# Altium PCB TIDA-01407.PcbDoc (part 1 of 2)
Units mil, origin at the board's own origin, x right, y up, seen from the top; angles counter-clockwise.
Board outline 6000 x 3000 mil, 4 copper layers (Top Layer, Signal Layer 1, Signal Layer 2, Bottom Layer), stack 79.834 mil thick; 145 components, 63 nets, 415 pads, 195 vias.
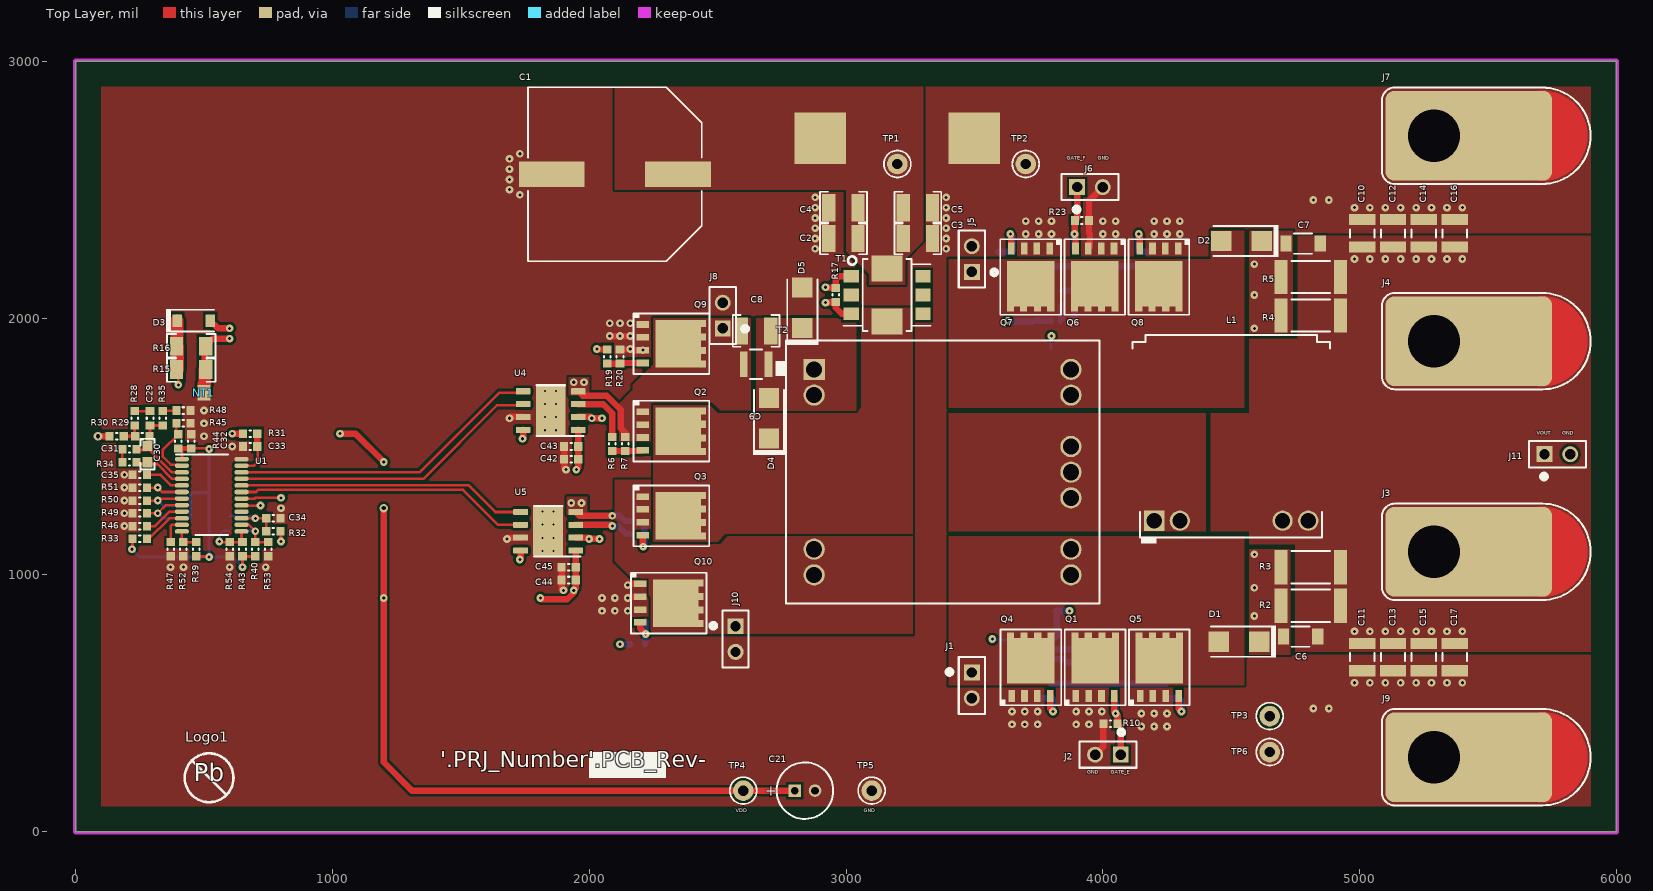
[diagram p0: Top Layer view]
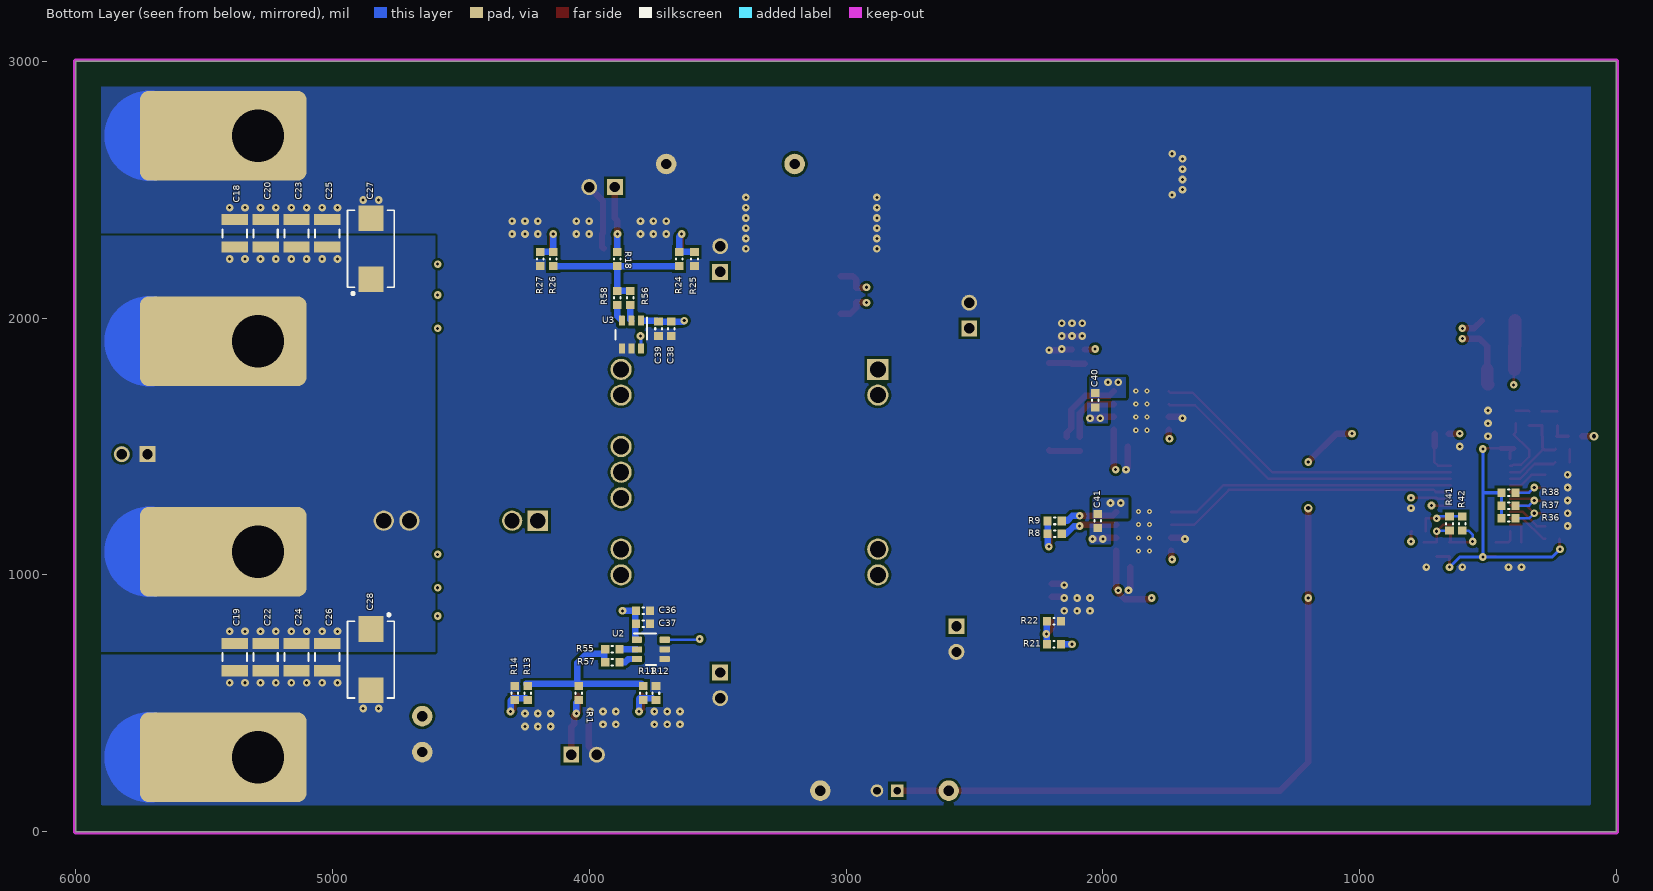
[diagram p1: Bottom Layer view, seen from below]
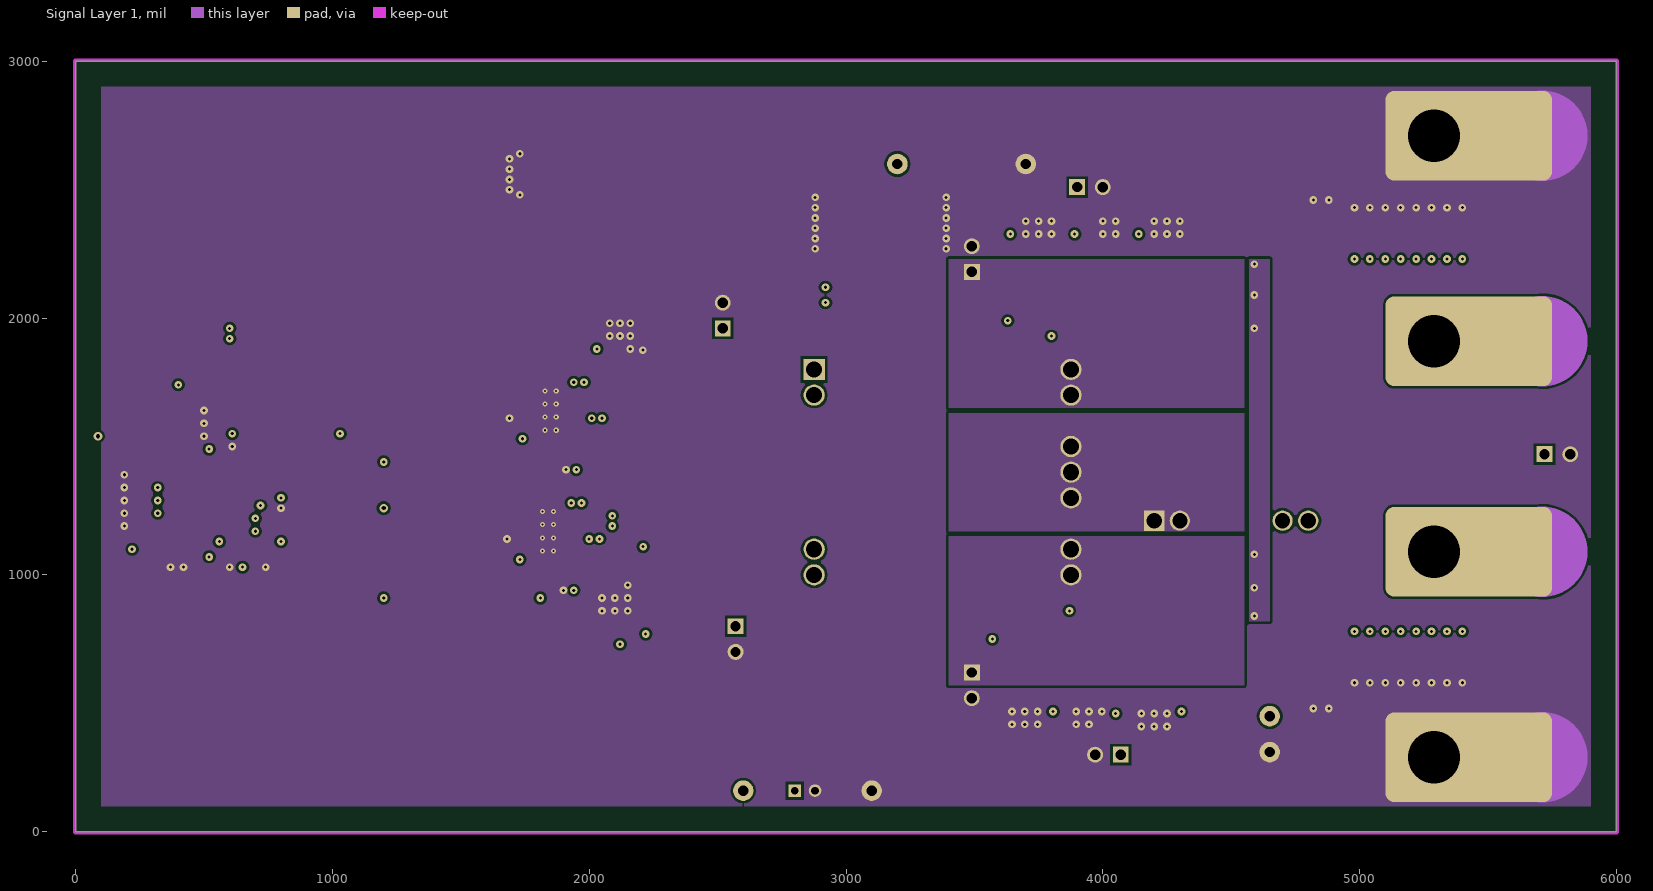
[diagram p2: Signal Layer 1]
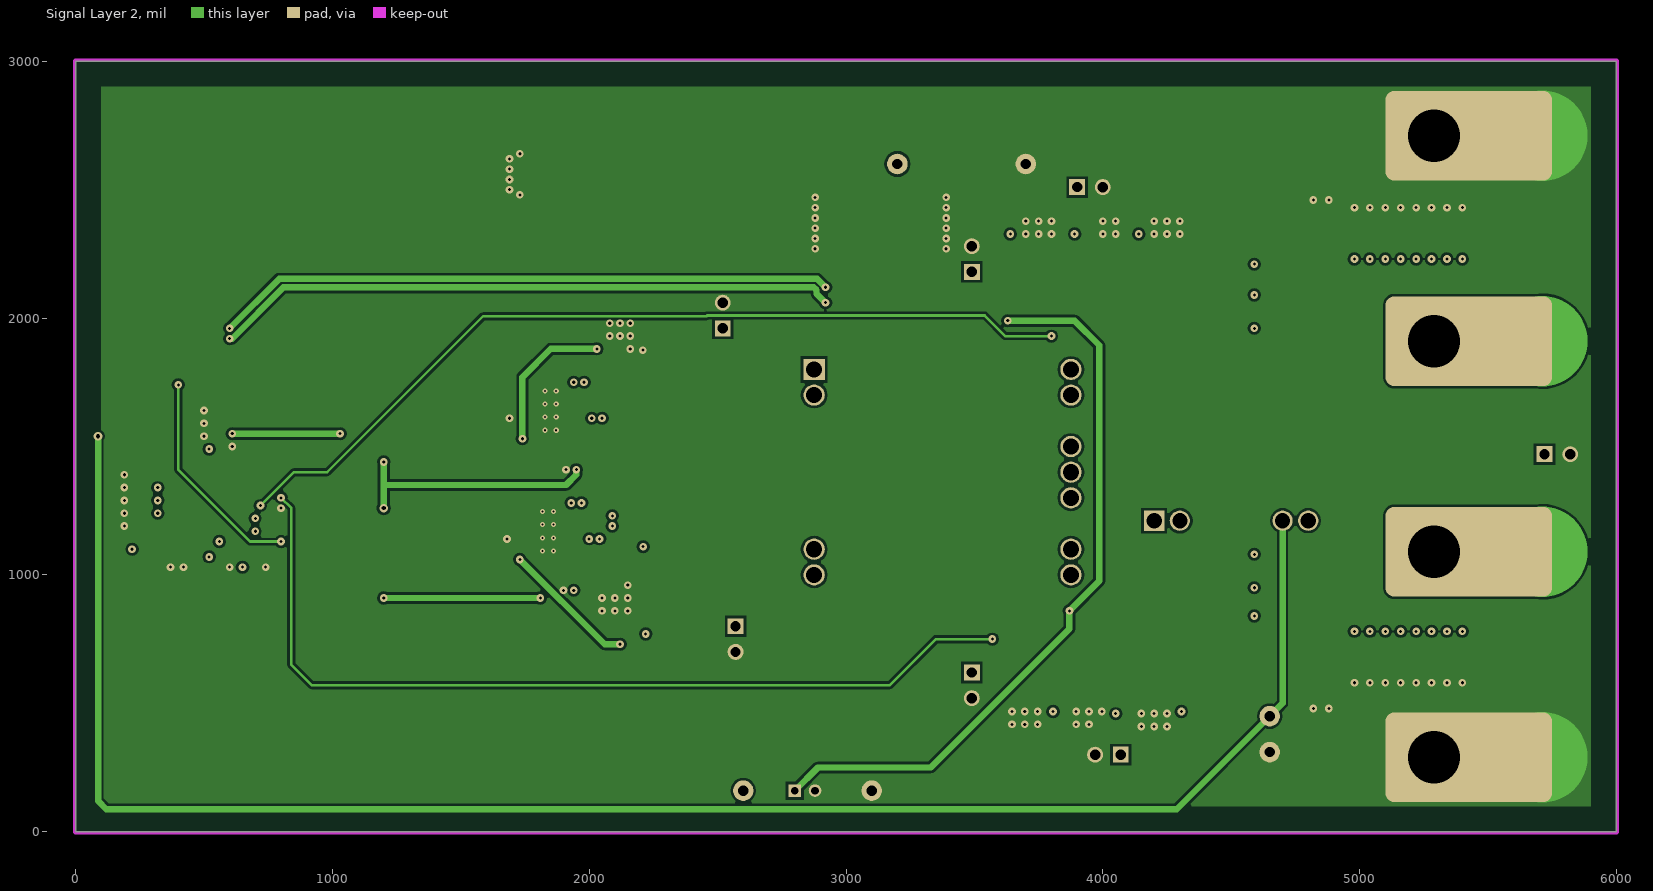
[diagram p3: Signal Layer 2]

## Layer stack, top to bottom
Top Solder: solder mask 0.4, Solder Resist, Dk 3.5
Top Layer: signal copper 1.4
Dielectric1: core 59.2, FR-4, Dk 4.8
Signal Layer 1: signal copper 1.417
Dielectric 3: prepreg 5, Dk 4.2
Signal Layer 2: signal copper 1.417
Dielectric 2: core 10, Dk 4.2
Bottom Layer: signal copper 1.4
Bottom Solder: solder mask 0.4, Solder Resist, Dk 3.5

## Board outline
0,0 6000,0 6000,3000 0,3000

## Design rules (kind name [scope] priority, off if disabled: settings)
AcuteAngle [All] p1: minimum=4.50000000000000E+0001 checktracksonly=FALSE
AssemblyTestPointUsage [All] p1: valid=2
Clearance Clearance_BoardEdge_MountingHoles [OnCopper and InComponentClass('Mounting Holes') vs IsKeepOut] p1: gap=40
Clearance Clearance_BoardEdge_Poly [OnCopper and InPoly vs IsKeepOut] p2: gap=25
Clearance Clearance_BoardEdge [OnCopper and Not InComponentClass('Logo') and not InComponentClass('FiducialMark') and not InRegion(1000,500,4000,800) and Not IsKeepout vs IsKeepOut] p3: gap=70
Clearance Clearance_Poly [InPolygon] p4: gap=10
Clearance [All] p5: gap=7.5
ComponentClearance ComponentClearance_ScrewToNut [(HasFootprint('NY PMS 440 0025 PH')) vs (HasFootprint('Keystone_1902C'))] p1: gap=5 collisioncheckmode=3 verticalgap=10 showdistances=FALSE
ComponentClearance ComponentClearance_MountingHoles [InComponentClass('Mounting Holes')] p2: gap=20 collisioncheckmode=3 verticalgap=100000 showdistances=FALSE
ComponentClearance ComponentClearance_SmallPassives [HasFootprint('0201*') or HasFootprint('0402*') or HasFootprint('0508') or HasFootprint('0603*') or HasFootprint('0612') or HasFootprint('0805*') or HasFootprint('0815*') or HasFootprint('0830*') or HasFootprint('1206*') or HasFootprint('1210*') or HasFootprint('1808*') or HasFootprint('1812*') or HasFootprint('1825*') or HasFootprint('2010*') or HasFootprint('2220*') or HasFootprint('2225*') or HasFootprint('2512*') or HasFootprint('2728*') or HasFootprint('3518*') vs HasFootprint('0201*') or HasFootprint('0402*') or HasFootprint('0508') or HasFootprint('0603*') or HasFootprint('0612') or HasFootprint('0805*') or HasFootprint('0815*') or HasFootprint('0830*') or HasFootprint('1206*') or HasFootprint('1210*') or HasFootprint('1808*') or HasFootprint('1812*') or HasFootprint('1825*') or HasFootprint('2010*') or HasFootprint('2220*') or HasFootprint('2225*') or HasFootprint('2512*') or HasFootprint('2728*') or HasFootprint('3518*')] p3: gap=10 collisioncheckmode=3 verticalgap=10 showdistances=FALSE
ComponentClearance ComponentClearance_THtoSMT [IsThruComponent vs IsSMTComponent] p4: gap=1 collisioncheckmode=3 verticalgap=0 showdistances=FALSE
ComponentClearance ComponentClearance_THtoTH [IsThruComponent vs IsThruComponent] p5: gap=20 collisioncheckmode=3 verticalgap=100000 showdistances=FALSE
ComponentClearance [All] p6: gap=20 collisioncheckmode=3 verticalgap=0 showdistances=FALSE
DiffPairsRouting [All] p1: maxlimit=100 minlimit=10 mostfreqgap=10 toplayer_minwidth=15 toplayer_maxwidth=15 toplayer_prefwidth=15 midlayer1_minwidth=15 midlayer1_maxwidth=15 midlayer1_prefwidth=15 midlayer2_minwidth=15 midlayer2_maxwidth=15 midlayer2_prefwidth=15 bottomlayer_minwidth=15 bottomlayer_maxwidth=15 bottomlayer_prefwidth=15 maxuncoupledlength=1000
FabricationTestPointUsage TestPointUsage [All] p1: valid=2 allowmultiple=FALSE
FabricationTestpoint Testpoint [All] p1: side=3 testpointundercomponent=TRUE minsize=40 maxsize=100 preferedsize=60 minholesize=0 maxholesize=40 preferedholesize=32 testpointgrid=1 allowsidetop=TRUE allowsidebottom=TRUE usegrid=TRUE gridtolerance=0.01
FanoutControl Fanout_LCC [IsLCC] p1: bgadir=Out bgaviamode=Centered fanoutstyle=Auto fanoutdirection=Alternating viagrid=1 // Fanout_LCC (Default Rule)
FanoutControl Fanout_BGA [IsBGA] p2: bgadir=Out bgaviamode=Centered fanoutstyle=Auto fanoutdirection=Alternating viagrid=1 // Fanout_BGA (Default Rule)
FanoutControl Fanout_Default [All] p4: bgadir=Out bgaviamode=Centered fanoutstyle=Auto fanoutdirection=Alternating viagrid=1 // Fanout_Default (Default Rule)
FanoutControl Fanout_Small [(CompPinCount < 5)] p5: bgadir=Out bgaviamode=Centered fanoutstyle=Auto fanoutdirection=OutThenIn viagrid=1 // Fanout_Small (Default Rule)
HoleSize [All] p1: absolutevalues=TRUE maxlimit=251 minlimit=7 maxpercent=80.000 minpercent=20.000
MinimumAnnularRing [All] p1: minimumring=5
MinimumSolderMaskSliver MinimumSolderMaskSliver_Logo [InComponentClass('Logo') vs InComponentClass('Logo')] p1: minsoldermaskwidth=0
MinimumSolderMaskSliver SilkscreenOverComponentPads [All] p2: minsoldermaskwidth=0
MinimumSolderMaskSliver [All] p3: minsoldermaskwidth=0
PlaneConnect [All] p1: planeconnectstyle=Direct reliefexpansion=10 reliefentries=4 reliefconductorwidth=10 reliefairgap=10
PolygonConnect [All] p1: connectstyle=Direct reliefconductorwidth=10 reliefentries=4 polygonreliefangle="90 Angle" airgapwidth=10
RoutingVias [All] p1: holewidth=16 width=34 viastyle="Through Hole" minholewidth=7 minwidth=19 maxholewidth=40 maxwidth=65
SMDToCorner [All] p1: distance=0
SilkToBoardRegionClearance [Not ((IsComment or IsDesignator) And (Hide <> 'False')) and not InRegion(1000,500,4000,800)] p1:
SilkToSilkClearance [All] p1: silktosilkclearance=0
SilkToSolderMaskClearance [IsPad] p1: minsilkscreentomaskgap=0 clearancetoexposedcopper=TRUE
SolderMaskExpansion [All] p1: expansion=3
Width [All] p1: maxlimit=100 minlimit=6 preferedwidth=10 checkconnectedcopper=TRUE
15 further rules are at their usual default settings.

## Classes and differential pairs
component class "Gate Drivers High Side and Low Side": C36 C37 C38 C39 C40 C41 C42 C43 C44 C45 C47 C48 C51 C52 C55 D8 D10 D11 D12 D13 D14 D15 D17 D18 D19 D20 D21 D22 D24 D25 Logo1 Q12 Q15 Q16 R55 R56 R57 R58 R62 R64 T5 U2 U3 U4 U5
component class "400W Phase Shifted Full Bridge": C1 C2 C3 C4 C5 C6 C7 C8 C9 C10 C11 C12 C13 C14 C15 C16 C17 C18 C19 C20 C21 C22 C23 C24 C25 C26 C27 C28 C29 C30 C31 C32 C33 C34 C35 D1 D2 D3 D4 D5 J1 J2 J3 J4 J5 J6 J7 J8 J9 J10 J11 L1 NT1 Q1 Q2 Q3 Q4 Q5 Q6 Q7 Q8 Q9 Q10 R1 R2 R3 R4 R5 R6 R7 R8 R9 R10 R11 R12 R13 R14 R15 R16 R17 R18 R19 R20 R21 R22 R23 R24 R25 R26 R27 R28 R29 R30 R31 R32 R33 R34 R35 R36 R37 R38 R39 R40 R41 R42 R43 R44 R45 R46 R47 R48 R49 R50 R51 R52 R53 R54 T1 T2 TP1 TP2 TP3 TP4 TP5 TP6 U1

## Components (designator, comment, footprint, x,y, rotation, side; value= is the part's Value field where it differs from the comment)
C1 "EEV-FK2A151M" SM_RADIAL_J16 2100,2560 r180 top
C2 "GRM32ER72A225KA35L" 1210_270 2990,2310 r180 top
C3 "GRM32ER72A225KA35L" 1210_270 3280,2310 r0 top
C4 "GRM32ER72A225KA35L" 1210_270 2990,2430 r180 top
C5 "GRM32ER72A225KA35L" 1210_270 3280,2430 r0 top
C6 "GRM31CR72E104KW03L" 1206_180 4770,760 r0 top
C7 "GRM31CR72E104KW03L" 1206_180 4780,2290 r0 top
C8 "GRM32ER72A225KA35L" 1210_270 2650,1950 r0 top
C9 "170nH Custom Shim" DFE322512C 2650,1820 r180 top
C10 "GRM32ER71E226KE15L" 1210_270L 5010,2330 r90 top
C11 "GRM32ER71E226KE15L" 1210_270L 5010,680 r270 top
C12 "GRM32ER71E226KE15L" 1210_270L 5130,2330 r90 top
C13 "GRM32ER71E226KE15L" 1210_270L 5130,680 r270 top
C14 "GRM32ER71E226KE15L" 1210_270L 5250,2330 r90 top
C15 "GRM32ER71E226KE15L" 1210_270L 5250,680 r270 top
C16 "GRM32ER71E226KE15L" 1210_270L 5370,2330 r90 top
C17 "GRM32ER71E226KE15L" 1210_270L 5370,680 r270 top
C18 "GRM32ER71E226KE15L" 1210_270L 5380,2330 r90 bottom
C19 "GRM32ER71E226KE15L" 1210_270L 5380,680 r270 bottom
C20 "GRM32ER71E226KE15L" 1210_270L 5260,2330 r90 bottom
C21 "EKZE350ELL330ME11D" Chemi-Con_500x1100 2840,160 r0 top
C22 "GRM32ER71E226KE15L" 1210_270L 5260,680 r270 bottom
C23 "GRM32ER71E226KE15L" 1210_270L 5140,2330 r90 bottom
C24 "GRM32ER71E226KE15L" 1210_270L 5140,680 r270 bottom
C25 "GRM32ER71E226KE15L" 1210_270L 5020,2330 r90 bottom
C26 "GRM32ER71E226KE15L" 1210_270L 5020,680 r270 bottom
C27 "16TQC150MYF" 7343-31 4850,2270 r90 bottom
C28 "16TQC150MYF" 7343-31 4850,670 r270 bottom
C29 "GRM1885C1H470JA01D" 0603L 290,1610 r90 top
C30 "GRM1885C1H331JA01D" 0603 280,1470 r90 top
C31 "GRM188R71H103KA01D" 0603L 210,1489.33 r0 top
C32 "GRM188R71E105KA12D" 0603L 450,1520 r90 top
C33 "GRM188R71E105KA12D" 0603L 680,1500 r180 top
C34 "GRM1885C1H821JA01D" 0603L 770,1220 r0 top
C35 "GRM188R71H473KA61D" 0603L 250,1390 r180 top
C36 "GRM188R71E105KA12D" 0603L 3790,860 r180 bottom
C37 "GRM188R71H104KA93D" 0603L 3790,810 r180 bottom
C38 "GRM188R71E105KA12D" 0603L 3680,1958.5 r270 bottom
C39 "GRM188R71H104KA93D" 0603L 3730,1958.5 r270 bottom
C40 "GRM188R71H104KA93D" 0603L 2030,1680 r90 bottom
C41 "GRM188R71H104KA93D" 0603L 2020,1210 r90 bottom
C42 "GRM188R71E105KA12D" 0603L 1930,1450 r180 top
C43 "GRM188R71H104KA93D" 0603L 1930,1500 r180 top
C44 "GRM188R71E105KA12D" 0603L 1920,980 r180 top
C45 "GRM188R71H104KA93D" 0603L 1920,1030 r180 top
D1 "ES1D" SMA 4530,740 r180 top
D2 "ES1D" SMA 4540,2300 r180 top
D3 "1N4148W-7-F" SOD-123 460,1990 r0 top
D4 "ES1D" SMA 2700,1610 r90 top
D5 "ES1D" SMA 2830,2040 r90 top
J1 "PPTC021LFBN-RC" CONN_PPTC021LFBN-RC 3490,570 r90 top
J2 "PPTC021LFBN-RC" CONN_PPTC021LFBN-RC 4020,300 r0 top
J3 "L35" TB_L35 5290,1090 r0 top
J4 "L35" TB_L35 5290,1910 r0 top
J5 "PPTC021LFBN-RC" CONN_PPTC021LFBN-RC 3490,2230 r270 top
J6 "PPTC021LFBN-RC" CONN_PPTC021LFBN-RC 3950,2510 r180 top
J7 "L35" TB_L35 5290,2710 r0 top
J8 "PPTC021LFBN-RC" CONN_PPTC021LFBN-RC 2520,2010 r270 top
J9 "L35" TB_L35 5290,290 r0 top
J10 "PPTC021LFBN-RC" CONN_PPTC021LFBN-RC 2570,750 r90 top
J11 "PPTC021LFBN-RC" CONN_PPTC021LFBN-RC 5770,1470 r180 top
L1 "59024" 59024 4500,1540 r90 top
Logo1 "Pb-Free Symbol" Pb-Free_Overlay_Medium 520,210 r0 top
NT1 "Net-Tie" Net-Tie_50milWide_30milLong 500,1710 r90 top net-tie
Q1 "BSC057N08NS3 G" PG-TDSON-8 3970,640 r90 top
Q2 "BSC072N08NS5" PG-TDSON-8 2320,1560 r0 top
Q3 "BSC072N08NS5" PG-TDSON-8 2320,1230 r0 top
Q4 "BSC057N08NS3 G" PG-TDSON-8 3720,640 r90 top
Q5 "BSC057N08NS3 G" PG-TDSON-8 4220,640 r90 top
Q6 "BSC057N08NS3 G" PG-TDSON-8 3968.54,2160 r270 top
Q7 "BSC057N08NS3 G" PG-TDSON-8 3718.54,2160 r270 top
Q8 "BSC057N08NS3 G" PG-TDSON-8 4218.54,2160 r270 top
Q9 "BSC072N08NS5" PG-TDSON-8 2320,1900 r0 top
Q10 "BSC072N08NS5" PG-TDSON-8 2310,890 r0 top
R1 "CRCW06032R20JNEA" 0603L 4040,540 r90 bottom
R2 "CRCW25125K10JNEH" 2512 4810,880 r180 top
R3 "CRCW25125K10JNEH" 2512 4810,1030 r180 top
R4 "CRCW25125K10JNEH" 2512 4810,2010 r180 top
R5 "CRCW25125K10JNEH" 2512 4810,2160 r180 top
R6 "CRCW06030000Z0EA" 0603L 2090,1510 r270 top
R7 "CRCW060310K0FKEA" 0603L 2140,1510 r270 top
R8 "CRCW06030000Z0EA" 0603L 2187.56,1160 r0 bottom
R9 "CRCW060310K0FKEA" 0603L 2187.56,1210 r0 bottom
R10 "CRCW060310K0FKEA" 0603L 4030,420 r0 top
R11 "CRCW06032R20JNEA" 0603L 3790,540 r270 bottom
R12 "CRCW060310K0FKEA" 0603L 3740,540 r270 bottom
R13 "CRCW06032R20JNEA" 0603L 4240,540 r270 bottom
R14 "CRCW060310K0FKEA" 0603L 4290,540 r270 bottom
R15 "CRCW120610R0FKEA" 1206 450,1800 r180 top
R16 "CRCW120649R9FKEA" 1206 450,1890 r180 top
R17 "CRCW060310K0FKEA" 0603L 2960,2090 r90 top
R18 "CRCW06032R20JNEA" 0603L 3890,2230 r270 bottom
R19 "CRCW06030000Z0EA" 0603L 2070,1850 r270 top
R20 "CRCW060310K0FKEA" 0603L 2120,1850 r270 top
R21 "CRCW06030000Z0EA" 0603L 2190,730 r0 bottom
R22 "CRCW060310K0FKEA" 0603L 2190,820 r0 bottom
R23 "CRCW060310K0FKEA" 0603L 3918.54,2380 r180 top
R24 "CRCW06032R20JNEA" 0603L 3650,2230 r90 bottom
R25 "CRCW060310K0FKEA" 0603L 3590,2230 r90 bottom
R26 "CRCW06032R20JNEA" 0603L 4140,2230 r90 bottom
R27 "CRCW060310K0FKEA" 0603L 4190,2230 r90 bottom
R28 "CRCW06030000Z0EA" 0603L 230,1610 r90 top
R29 "CRCW060313K3FKEA" 0603L 260,1540 r180 top
R30 "CRCW060349R9FKEA" 0603L 160,1540 r180 top
R31 "CRCW060310R0JNEA" 0603L 680,1550 r180 top
R32 "CRCW0603100RFKEA" 0603L 770,1170 r0 top
R33 "CRCW060318K2FKEA" 0603L 250,1140 r180 top
R34 "CRCW060310K0FKEA" 0603L 210,1439.33 r0 top
R35 "CRCW06031K96FKEA" 0603L 340,1610 r270 top
R36 "CRCW060310K0FKEA" 0603L 420,1220 r0 bottom
R37 "CRCW060310K0FKEA" 0603L 420,1270 r0 bottom
R38 "CRCW060310K0FKEA" 0603L 420,1320 r0 bottom
R39 "CRCW060319K1FKEA" 0603L 470,1100 r270 top
R40 "CRCW060310K0FKEA" 0603L 700,1100 r270 top
R41 "CRCW06030000Z0EA" 0603L 650,1200 r90 bottom
R42 "CRCW06030000Z0EA" 0603L 600,1200 r90 bottom
R43 "CRCW060310K0FKEA" 0603L 650,1100 r270 top
R44 "CRCW060310K0FKEA" 0603L 400,1520 r270 top
R45 "CRCW060310K0FKEA" 0603L 420,1590 r180 top
R46 "CRCW060360K4FKEA" 0603L 250,1190 r0 top
R47 "CRCW060320K0FKEA" 0603L 370,1100 r90 top
R48 "CRCW06031K54FKEA" 0603L 420,1640 r180 top
R49 "RC0603FR-0713KL" 0603L 250,1239.33 r0 top
R50 "RC0603FR-0713KL" 0603L 250,1289.33 r0 top
R51 "RC0603FR-0713KL" 0603L 250,1339.33 r0 top
R52 "CRCW06031K00FKEA" 0603L 420,1100 r90 top
R53 "CRCW060310K0FKEA" 0603L 750,1100 r90 top
R54 "CRCW060310K0FKEA" 0603L 600,1100 r90 top
R55 "CRCW06030000Z0EA" 0603L 3910,710 r180 bottom
R56 "CRCW06030000Z0EA" 0603L 3840,2078.5 r270 bottom
R57 "CRCW06030000Z0EA" 0603L 3910,660 r180 bottom
R58 "CRCW06030000Z0EA" 0603L 3890,2078.5 r270 bottom
T1 "PA1005.100NL" P82xx 3160,2090 r0 top
T2 "59023" Payton_59023 3375.98,1400 r0 top
TP1 "5000" Keystone5000 3200,2600 r0 top
TP2 "5001" Keystone5001 3700,2600 r0 top
TP3 "5000" Keystone5000 4650,450 r0 top
TP4 "5000" Keystone5000 2600,160 r0 top
TP5 "5001" Keystone5001 3100,160 r0 top
TP6 "5001" Keystone5001 4650,310 r0 top
U1 "UCC28951-Q1" PW0024A_N 530,1310 r0 top
U2 "UCC27511A-Q1" DBV0006A_N 3760,710 r180 bottom
U3 "UCC27511A-Q1" DBV0006A_N 3835.67,1935.81 r270 bottom
U4 "UCC27212A-Q1" DDA0008E_N 1850,1640 r180 top
U5 "UCC27212A-Q1" DDA0008E_N 1840,1170 r180 top

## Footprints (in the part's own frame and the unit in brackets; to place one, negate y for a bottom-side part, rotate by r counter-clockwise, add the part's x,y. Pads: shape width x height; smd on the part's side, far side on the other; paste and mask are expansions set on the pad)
0603 [mm] "0603 from SM-752 data"
  rect 1x0.95 smd: 1(-0.8,0) 2(0.8,0)
  silkscreen extent -1.52,-0.69 1.52,0.69, body extent -0.87,-0.47 0.87,0.47, height 1
0603L [mm] "0603 from SM-752 data"
  rect 0.8x0.85 smd: 1(-0.7,0) 2(0.7,0)
  silkscreen extent -0.07,-0.33 0.07,0.33, body extent -0.87,-0.47 0.87,0.47, height 1
1206 [mm] "1206 from SM-752 data"
  rect 1.3x1.85 smd: 1(-1.45,0) 2(1.45,0)
  silkscreen extent -2.4,-1.21 2.4,1.21, body extent -1.7,-0.9 1.7,0.9, height 1.35
1206_180 [mm] "1206_180"
  rect 1.1x1.6 smd: 1(-1.7,0) 2(1.7,0)
  silkscreen extent -0.9,-1 0.9,1, body extent -1.75,-0.95 1.75,0.95, height 1.8
1210_270 [mm] "1210"
  rect 1.3x2.7 smd: 1(-1.45,0) 2(1.45,0)
  silkscreen extent -2.32,-1.57 2.32,1.57, body extent -1.7,-1.35 1.7,1.35, height 2.7
1210_270L [mm] "1210"
  rect 1.1x2.6 smd: 1(-1.35,0) 2(1.35,0)
  silkscreen extent -0.4,-1.2 0.4,1.2, body extent -1.7,-1.35 1.7,1.35, height 2.7
2512 [mm] "Chip Resistor, Body 6.3x3.2mm, IPC Medium Density"
  rect 1.3x3.4 smd: 1(-2.95,0) 2(2.95,0)
  silkscreen extent -1.9,-1.6 1.9,1.6, body extent -3.22,-1.67 3.22,1.67, height 0.71
7343-31 [mm] "Medium Density based on Kemet T495 dimensions"
  rect 2.55x2.45 smd: 1(-3.025,0) 2(3.025,0)
  silkscreen extent -4.56,-2.3 3.8,2.3, body extent -3.8,-2.3 3.8,2.3, height 3.1
59024 [mm] "TH, 4-Leads, Body 20x19.5mm"
  rect 2x2 hole 1.5: 1(-8.355,7.62)
  round 2 hole 1.5: 2(-8.355,5.08) 6(-8.355,-5.08) 7(-8.355,-7.62)
  silkscreen extent -10.6,-9.75 10,9.75, body extent -10,-9.75 10,9.75, height 12
Chemi-Con_500x1100 [mm] "TH, 2-Leads, Dia 5mm, Lead Sapcing 2mm"
  rect 1.25x1.25 hole 0.75: 1(-1,0)
  round 1.25 hole 0.75: 2(1,0)
  silkscreen extent -2.8,-2.8 2.8,2.8, body extent -2.75,-2.75 2.75,2.75, height 12.5
CONN_PPTC021LFBN-RC [mil] "SULLINS"
  rect 62x62 hole 40: 1(50,0)
  round 62 hole 40.16: 2(-50,0)
  silkscreen extent -111,-51 111,97, body extent -110,-50 110,50, height 336
DBV0006A_N [mm] "SOT23, 6-Leads, Body 2.9x1.6mm, Pitch 0.95mm, Lead Span 2.8mm, IPC Medium Density"
  rrect17% 1x0.6 smd: 1(-1.375,0.95) 2(-1.375,0) 3(-1.375,-0.95) 4(1.375,-0.95) 5(1.375,0) 6(1.375,0.95)
  silkscreen extent -1.68,-1.55 0.5,1.55, body extent -1.42,-1.46 1.42,1.46, height 1.12
DDA0008E_N [mm]
  rrect17% 1.45x0.6 smd: 1(-2.725,1.905) 2(-2.725,0.635) 3(-2.725,-0.635) 4(-2.725,-1.905) 5(2.725,-1.905) 6(2.725,-0.635) 7(2.725,0.635) 8(2.725,1.905)
  rrect7% 2.95x4.9 smd paste-1.5 mask-1.5: 9(0,0)
  rrect4% 2.4x3.1 on Top Paste: 9(0,0)
  rrect4% 2.4x3.1 on Top Solder: 9(0,0)
  silkscreen extent -3.22,-2.5 1.4,2.5, body extent -3,-2.45 3,2.45, height 1.57
DFE322512C [mm] "TOKO, Pad sizes increased as per request"
  rect 0.75x2.5 smd: 1(-1.225,0) 2(1.225,0)
  silkscreen extent -0.6,-1.45 0.6,1.45, body extent -1.7,-1.35 1.7,1.35, height 1.2
Keystone5000 [mil] "For Keystone 500x miniature loop terminals"
  round 80 hole 40: 1(0,0)
  silkscreen extent -52,-52 52,52, body extent -49,-49 49,49, height 182
Keystone5001 [mil] "For Keystone 500x miniature loop terminals"
  round 80 hole 40: 1(0,0)
  silkscreen extent -52,-52 52,52, body extent -49,-49 49,49, height 182
Net-Tie_50milWide_30milLong [mil] "50mil net tie, no solder mask opening, no solder paste"
  rect 30x50 smd paste-20 mask-20: 1(-15,0) 2(15,0)
P82xx [mil] "Pulse recommended land pattern"
  rect 60x50 smd: 1(-140,73) 2(-140,0) 3(-140,-73) 4(140,-73) 5(140,0) 6(140,73)
  rect 120x100 smd: 7(0,-103) 8(0,103)
  silkscreen extent -170,-140 170,150, body extent -95,-140 95,140, height 215
Payton_59023 [mm] "TH, 11-Leads, Body 31x26mm, Pitch 2.54mm"
  rect 2.1x2.1 hole 1.6: 1(-12.7,10.16)
  round 2.1 hole 1.6: 2(-12.7,7.62) 8(-12.7,-7.62) 9(-12.7,-10.16) 10(12.7,-10.16) 11(12.7,-7.62) 13(12.7,-2.54) 14(12.7,0) 15(12.7,2.54) 17(12.7,7.62) 18(12.7,10.16)
  silkscreen extent -16.5,-13 15.5,13, body extent -15.5,-13 15.5,13, height 18
Pb-Free_Overlay_Medium [mil]
  silkscreen extent -95,-95 95,95
PG-TDSON-8 [mm] "Infineon recommended land pattern"
  rect 1.2x0.65 smd: 1(-2.825,1.905) 2(-2.825,0.635) 3(-2.825,-0.635) 4(-2.825,-1.905)
  rect 0.5x0.7 smd: 5(3.175,-2) 6(3.175,-0.675) 7(3.175,0.675) 8(3.175,2)
  rect 4.5x4.7 smd paste-2.25: 9(0.675,0)
  silkscreen extent -3.74,-3 3.74,3, body extent -3.17,-2.89 3.17,2.9, height 1.1
PW0024A_N [mm] "TSOP, 24-Leads, Body 7.8x4.4mm, Pitch 0.65mm, IPC Medium Density"
  oval 1.4x0.45 smd: 1(-2.95,3.575) 2(-2.95,2.925) 3(-2.95,2.275) 4(-2.95,1.625) 5(-2.95,0.975) 6(-2.95,0.325) 7(-2.95,-0.325) 8(-2.95,-0.975) 9(-2.95,-1.625) 10(-2.95,-2.275) 11(-2.95,-2.925) 12(-2.95,-3.575) 13(2.95,-3.575) 14(2.95,-2.925) 15(2.95,-2.275) 16(2.95,-1.625) 17(2.95,-0.975) 18(2.95,-0.325) 19(2.95,0.325) 20(2.95,0.975) 21(2.95,1.625) 22(2.95,2.275) 23(2.95,2.925) 24(2.95,3.575)
  silkscreen extent -3.51,-3.95 1.6,4.04, body extent -3.21,-3.9 3.21,3.9, height 1
SM_RADIAL_J16 [mm] "16 x 16.5mm:  Panasonic J16"
  rect 6.5x2.5 smd: 1(-6.25,0) 2(6.25,0)
  silkscreen extent -8.6,-8.6 8.6,8.6, body extent -8.6,-8.6 8.6,8.6, height 17
SMA [mm] "Molded Diode, 2-Leads, Body 4.3x2.6mm, IPC Medium Density, based on OnSemi component dimensions and land pattern"
  rect 2x2 smd: 1(-2,0) 2(2,0)
  silkscreen extent -3.66,-1.57 2.79,1.57, body extent -2.6,-1.3 2.6,1.3, height 2.42
SOD-123 [mm] "On Semi recommended land pattern"
  rect 0.915x1.22 smd: 1(-1.637,0) 2(1.637,0)
  silkscreen extent -2.74,-1.17 2.03,1.17, body extent -1.93,-0.9 1.93,0.9, height 1.35
TB_L35 [mm] "Connector, L Type Copper Single Conductor, TH"
  rrect20% 16.51x8.89 hole 5.16 copper offset 3.429,0: 1(0,0)
  Multi-Layer circle w4.47: c10.7,0 r2.235
  silkscreen extent -5.16,-4.76 15.48,4.76, body extent -5.16,-4.76 15.48,4.76, height 9.53

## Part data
C1: "CAP, AL, 150 μF, 100 V, +/- 20%, 0.17 ohm, AEC-Q200 Grade 2, SMD"
C2 C3 C4 C5 C8: "CAP, CERM, 2.2 μF, 100 V, +/- 10%, X7R, 1210"
C6 C7: "CAP, CERM, 0.1 μF, 250 V, +/- 10%, X7R, 1206"
C9: library part 1277AS-H-R68M=P2, "Inductor, Flat Wire, 680 nH, 3.5 A, 0.035 ohm, SMD"
C10 C11 C12 C13 C14 C15 C16 C17 C18 C19 C20 C22 C23 C24 C25 C26: "CAP, CERM, 22 μF, 25 V, +/- 10%, X7R, 1210"
C21: "CAP, AL, 33 μF, 35 V, +/- 20%, TH"
C27 C28: "CAP, Tantalum Polymer, 150 μF, 16 V, +/- 20%, 0.05 ohm, 7343-31 SMD"
C29: "CAP, CERM, 47 pF, 50 V, +/- 5%, C0G/NP0, 0603"
C30: "CAP, CERM, 330 pF, 50 V, +/- 5%, C0G/NP0, 0603"
C31: "CAP, CERM, 0.01 μF, 50 V, +/- 10%, X7R, 0603"
C32 C33 C36 C38 C42 C44: "CAP, CERM, 1 μF, 25 V, +/- 10%, X7R, 0603"
C34: "CAP, CERM, 820 pF, 50 V, +/- 5%, C0G/NP0, 0603"
C35: "CAP, CERM, 0.047 μF, 50 V, +/- 10%, X7R, 0603"
C37 C39 C40 C41 C43 C45: "CAP, CERM, 0.1 μF, 50 V, +/- 10%, X7R, 0603"
D1 D2 D4 D5: library part ES1D-13-F, "Diode, Ultrafast, 200 V, 1 A, SMA"
D3: "Diode, Ultrafast, 100 V, 0.15 A, SOD-123"
J1 J2 J5 J6 J8 J10 J11: "Receptacle, 100mil, 2x1, Tin, TH"
J3 J4 J7 J9: "Connector, L Type Copper Single Conductor, TH"
L1: "Inductor, 1 μH, 47 A, TH"
Logo1: library part Pb-Free
NT1: "Single point connection between nets."
Q1 Q4 Q5 Q6 Q7 Q8: "MOSFET, N-CH, 80 V, 100 A, PG-TDSON-8"
Q2 Q3 Q9 Q10: library part BSC072N08NS5ATMA1, "MOSFET, N-CH, 80 V, 74 A, PG-TDSON-8"
R1 R11 R13 R18 R24 R26: "RES, 2.2, 5%, 0.1 W, 0603"
R2 R3 R4 R5: "RES, 5.1 k, 5%, 1 W, AEC-Q200 Grade 0, 2512"
R6 R8 R19 R21 R28 R41 R42 R55 R56 R57 R58: "RES, 0, 5%, 0.1 W, 0603"
R7 R9 R10 R12 R14 R17 R20 R22 R23 R25 R27 R34 R36 R37 R38 R40 R43 R44 R45 R53 R54: "RES, 10.0 k, 1%, 0.1 W, 0603"
R15: "RES, 10.0, 1%, 0.25 W, 1206"
R16: "RES, 49.9, 1%, 0.25 W, 1206"
R29: "RES, 13.3 k, 1%, 0.1 W, 0603"
R30: "RES, 49.9, 1%, 0.1 W, 0603"
R31: "RES, 10, 5%, 0.1 W, 0603"
R32: "RES, 100, 1%, 0.1 W, 0603"
R33: "RES, 18.2 k, 1%, 0.1 W, 0603"
R35: "RES, 1.96 k, 1%, 0.1 W, 0603"
R39: "RES, 19.1 k, 1%, 0.1 W, 0603"
R46: "RES, 60.4 k, 1%, 0.1 W, 0603"
R47: "RES, 20.0 k, 1%, 0.1 W, 0603"
R48: "RES, 1.54 k, 1%, 0.1 W, 0603"
R49 R50 R51: "RES, 13.0 k, 1%, 0.1 W, 0603"
R52: "RES, 1.00 k, 1%, 0.1 W, 0603"
T1: "SMT Current Sense Tranformer"
T2: "Transformer, TH"
TP1 TP3 TP4: "Test Point, Miniature, Red, TH"
TP2 TP5 TP6: "Test Point, Miniature, Black, TH"
U1: library part UCC28950PWR, "Green Phase-Shifted Full-Bridge Controller with Synchronous Rectification with Current Mode Control, 97 % Duty Cycle, -40 to +125 degC, 24-pin TSSOP (PW), Green (RoHS & no Sb/Br)"
U2 U3: library part UCC27511DBVR, "Single-Channel High-Speed Low-Side Gate Driver (with 4-A Peak Source and 8-A Peak Sink), DBV0006A (SOT-6)"
U4 U5: library part UCC27211AQDDARQ1, "120-V Boot, 4-A Peak, High Frequency High-Side and Low-Side Driver, DDA0008E (SOIC-8)"

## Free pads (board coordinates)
  rect 200x200 smd: 0(2900,2700) 0(3500,2700)

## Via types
v1: diameter 30, hole 12, Top Layer to Bottom Layer, 177 vias
v2: diameter 19.68, hole 7.87, Top Layer to Bottom Layer, tented both sides, 8 vias
v3: diameter 19.68, hole 7.87, Top Layer to Bottom Layer, 8 vias
v4: diameter 34, hole 16, Top Layer to Bottom Layer, 2 vias

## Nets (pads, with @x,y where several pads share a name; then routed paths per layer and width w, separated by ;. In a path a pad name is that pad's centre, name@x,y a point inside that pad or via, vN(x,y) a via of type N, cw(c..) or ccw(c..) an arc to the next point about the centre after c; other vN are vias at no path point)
10V_VDD: C21.1 C36.1 C37.1 C38.1 C39.1 C42.1 C43.1 C44.1 C45.1 R31.2 TP4.1 U2.1 U3.1 U4.1 U5.1 | length 8567.7
  Top Layer w25: v1(610,1550) R31.2@652.44,1550 ; v1(1030,1550) 1090,1550 v1(1200,1440) ; v4(1200,1260) v1(1200,910) 1200,270 1310,160 TP4.1@2600,160 C21.1@2800.63,160 ; v1(1810,910) 1815,905 1914.5,905 1940,930.5 v1(1940,940) 1947.56,947.56 C44.1@1947.56,980 C45.1@1947.56,1030 1947.56,1094.72 U5.1@1947.28,1095 ; v1(1950,1410) 1957.56,1417.56 C42.1@1957.56,1450 C43.1@1957.56,1500 1957.56,1564.72 U4.1@1957.28,1565
  Signal Layer 2 w25: v1(610,1550) v1(1030,1550) ; v1(1200,910) v1(1810,910) ; v4(1200,1260) 1200,1350 ; v1(1200,1440) 1200,1350 ; v1(1950,1410) 1950,1390 1910,1350 1200,1350 ; C21.1@2800.63,160 2890.63,250 3330,250 3870,790 v1(3870,860) 3986.22,976.22 3986.22,1893.78 3890,1990 v1(3630,1990)
  Bottom Layer w25: v1(3630,1990) 3633.94,1986.06 C38.1@3680,1986.06 C39.1@3730,1986.06 3733.88,1989.94 U3.1@3798.27,1989.94 ; U2.1@3817.29,755.35 3820.72,758.78 C36.1@3820.72,860 ; C36.1@3817.56,860 C36.1@3820.72,860 ; v1(3870,860) C36.1@3820.72,860
ADEL: R40.1 R41.1 R53.2 U1.14 | length 207.6
  Top Layer w10: U1.14@646.14,1194.84 675.16,1194.84 v1(700,1170) R40.1@700,1127.56 R53.2@750,1127.56
  Bottom Layer w10: R41.1@650,1172.44 697.56,1172.44 v1(700,1170)
ADELEF: R42.1 R43.1 R54.2 U1.13 | length 207.6
  Top Layer w10: v1(560,1130) 562.44,1127.56 R54.2@600,1127.56 R43.1@650,1127.56 646.14,1131.42 U1.13@646.14,1169.25
  Bottom Layer w10: v1(560,1130) 560,1156.89 575.55,1172.44 R42.1@600,1172.44
CS: D3.1 R15.2 R16.2 R32.2 | length 1139.2
  Top Layer w10: R15.2@396.85,1800 400,1796.85 v1(400,1740) ; R32.2@797.56,1170 800,1167.56 v1(800,1130)
  Top Layer w50: D3.1@395.53,1990 395.53,1891.32 396.85,1890 R15.2@396.85,1800
  Signal Layer 2 w10: v1(400,1740) 400,1409.33 679.33,1130 v1(800,1130)
CS_FLT: C34.1 R32.1 R41.2 R42.2 U1.15 | length 249.6
  Top Layer w10: U1.15@646.14,1220.43 646.57,1220 v1(700,1220) C34.1@742.44,1220 R32.1@742.44,1170
  Bottom Layer w10: R42.2@600,1227.56 R41.2@650,1227.56 692.44,1227.56 v1(700,1220)
DCM: R39.1 R52.2 U1.12 | length 94.2
  Top Layer w10: U1.12@413.86,1169.25 413.86,1133.7 R52.2@420,1127.56 R39.1@470,1127.56
DELAB: R38.1 R51.2 U1.6 | length 224.4
  Top Layer w10: R51.2@277.56,1339.33 278.23,1340 v1(320,1340) 337.2,1322.8 U1.6@413.86,1322.8
  Bottom Layer w10: v1(320,1340) 340,1320 R38.1@392.44,1320
DELCD: R37.1 R50.2 U1.7 | length 220.3
  Top Layer w10: R50.2@277.56,1289.33 319.33,1289.33 v1(320,1290) 327.2,1297.2 U1.7@413.86,1297.2
  Bottom Layer w10: v1(320,1290) 340,1270 R37.1@392.44,1270
DELEF: R36.1 R49.2 U1.8 | length 230.4
  Top Layer w10: R49.2@277.56,1239.33 319.33,1239.33 v1(320,1240) 351.61,1271.61 U1.8@413.86,1271.61
  Bottom Layer w10: v1(320,1240) 340,1220 R36.1@392.44,1220
DRV_A: R6.1 U4.3 | length 239.7
  Top Layer w25: U4.3@1957.28,1665 2055,1665 2090,1630 R6.1@2090,1537.56
DRV_B: R19.1 U4.8 | length 652.7
  Top Layer w25: v1(1740,1530) 1742.72,1532.72 U4.8@1742.72,1565 ; v1(2030,1880) 2032.44,1877.56 R19.1@2070,1877.56
  Signal Layer 2 w25: v1(1740,1530) 1740,1770 1850,1880 v1(2030,1880)
DRV_C: R8.1 U5.3 | length 227.2
  Top Layer w25: U5.3@1947.28,1195 2085,1195 v1(2090,1190)
  Bottom Layer w25: v1(2090,1190) 2113.27,1190 2143.27,1160 R8.1@2160,1160
DRV_D: R21.1 U5.8 | length 605.3
  Top Layer w25: v1(1730,1060) 1732.72,1062.72 U5.8@1732.72,1095
  Signal Layer 2 w25: v1(1730,1060) 2060,730 v1(2120,730)
  Bottom Layer w25: v1(2120,730) R21.1@2162.44,730
DRV_E: R1.2 R11.1 R13.1 R55.1 R57.1 | length 702.4
  Bottom Layer w25: R11.1@3796.19,575.51 R1.2@4046.19,575.51 ; 3940.72,692.95 3941.5,692.95 ; R57.1@3941.5,660 3941.5,692.95 ; R55.1@3941.5,710 3941.5,692.95 ; R13.1@4246.19,575.51 R1.2@4046.19,575.51 ; 3941.5,692.95 4011.19,692.95 4046.19,657.95 R1.2@4046.19,575.51
DRV_F: R18.2 R24.1 R26.1 R56.1 R58.1 | length 876.4
  Bottom Layer w25: R56.1@3840,2106.06 R58.1@3890,2106.06 R18.2@3890,2202.44 ; R26.1@4140,2202.44 R18.2@3890,2202.44 ; R18.2@3890,2202.44 R24.1@3650,2202.44 R18.2@3890,2202.44
EA+: R44.1 R45.2 U1.2 | length 246.3
  Top Layer w10: R45.2@392.44,1590 392.44,1555.12 R44.1@400,1547.56 340,1487.56 340,1460 370.61,1429.39 400.77,1429.39 405,1425.16 U1.2@413.86,1425.16
FB: C29.1 C30.2 C31.2 R29.1 R35.2 U1.3 | length 363.2
  Top Layer w10: C30.2@280,1486.89 287.86,1486.89 375.18,1399.57 U1.3@413.86,1399.57
  Top Layer w12: C31.2@237.56,1489.33 240,1486.89 280,1486.89 287.56,1494.45 R29.1@287.56,1540 290,1542.44 C29.1@290,1582.44 R35.2@340,1582.44
GND: C1.2 C2.2 C3.2 C4.2 C5.2 C10.2 C11.2 C12.2 C13.2 C14.2 C15.2 C16.2 C17.2 C18.2 C19.2 C20.2 C21.2 C22.2 C23.2 C24.2 C25.2 C26.2 C27.2 C28.2 C32.2 C33.2 C34.2 C35.2 C36.2 C37.2 C38.2 C39.2 C42.2 C43.2 C44.2 C45.2 D5.2 J1.2 J2.2 J5.2 J6.2 J7.1 J8.2 J9.1 J10.2 J11.2 NT1.1 pad.0@3500,2700 Q1.1 Q1.2 Q1.3 Q4.1 Q4.2 Q4.3 Q5.1 Q5.2 Q5.3 Q6.1 Q6.2 Q6.3 Q7.1 Q7.2 Q7.3 Q8.1 Q8.2 Q8.3 Q9.1 Q9.2 Q9.3 Q10.1 Q10.2 Q10.3 R10.1 R12.1 R14.1 R20.1 R22.1 R23.1 R25.1 R27.1 R45.1 R46.1 R47.1 R48.1 R49.1 R50.1 R51.1 R52.1 R53.1 R54.1 TP2.1 TP5.1 TP6.1 U1.24 U2.4 U2.5 U3.4 U3.5 U4.7 U4.9@1850,1640 U5.7 U5.9@1840,1170 | length 977
  Top Layer w25: v1(1680,1140) 1685,1145 U5.7@1732.72,1145 ; v1(1690,1610) 1695,1615 U4.7@1742.72,1615 ; C45.2@1892.44,1030 C44.2@1892.44,980 1892.44,947.56 v1(1900,940) ; C43.2@1902.44,1500 C42.2@1902.44,1450 1902.44,1417.56 v1(1910,1410) ; v1(2080,1930) v1(2160,1930) v1@2165,1925 ; R20.1@2120,1877.56 2157.56,1877.56 v1(2160,1880) 2165,1875 v1(2208.78,1875) ; v1@2148.32,960 v1(2150,960) 2155,965 Q10.1@2198.78,965 ; v1(2150,910) 2155,915 Q10.2@2198.78,915 ; Q6.3@3943.54,2271.22 3950,2277.68 3950,2327.33 3946.1,2331.23 R23.1@3946.1,2380 3946.1,2456.1 J6.2@4000,2510 ; J2.2@3970,300 4002.44,332.44 R10.1@4002.44,420
  other v1: 4150,410 4200,410 4250,410 3646.19,417.95 3696.19,417.95 3746.19,417.95 3896.19,417.95 3946.19,417.95 4150,460 4200,460 4250,460 3646.19,467.95 3696.19,467.95 3746.19,467.95 3896.19,467.95 3946.19,467.95 3996.19,467.95 4820,480 4880,480 4980,580 5040,580 5100,580 5160,580 5220,580 5280,580 5340,580 5400,580 2050,860 2100,860 2150,860 2050,910 2100,910 370,1030 420,1030 600,1030 740,1030 190,1190 190,1240 800,1260 190,1290 190,1340 190,1390 610,1500 500,1540 500,1590 500,1640 2120,1930 2080,1980 2120,1980 2160,1980 2880,2270 3390,2270 2880,2310 3390,2310 3700,2327.33 3750,2327.33 3800,2327.33 4000,2327.33 4050,2327.33 4200,2327.33 4250,2327.33 4300,2327.33 2880,2350 3390,2350 3700,2377.33 3750,2377.33 3800,2377.33 4000,2377.33 4050,2377.33 4200,2377.33 4250,2377.33 4300,2377.33 2880,2390 3390,2390 2880,2430 3390,2430 4980,2430 5040,2430 5100,2430 5160,2430 5220,2430 5280,2430 5340,2430 5400,2430 4820,2460 4880,2460 2880,2470 3390,2470 1730,2480 1690,2500 1690,2540 1690,2580 1690,2620 1730,2640
  other v2: 1818.35,1093.23 1861.65,1093.23 1818.35,1246.77 1861.65,1246.77 1828.35,1563.23 1871.65,1563.23 1828.35,1716.77 1871.65,1716.77
  other v3: 1818.35,1144.41 1861.65,1144.41 1818.35,1195.59 1861.65,1195.59 1828.35,1614.41 1871.65,1614.41 1828.35,1665.59 1871.65,1665.59
NetC1_1: C1.1 C2.1 C3.1 C4.1 C5.1 pad.0@2900,2700 T1.8 TP1.1
NetC6_1: C6.1 C7.1 D1.1 D2.1 R2.2 R3.2 R4.2 R5.2
  other v1: 4590,840 4590,950 4590,1080 4590,1960 4590,2090 4590,2210
NetC6_2: C6.2 C7.2 C10.1 C11.1 C12.1 C13.1 C14.1 C15.1 C16.1 C17.1 C18.1 C19.1 C20.1 C22.1 C23.1 C24.1 C25.1 C26.1 C27.1 C28.1 J3.1 J4.1 J11.1 L1.6 L1.7 R2.1 R3.1 R4.1 R5.1 R30.2 TP3.1 | length 6972.8
  Top Layer w25: v4(87.5,1540) R30.2@132.44,1540
  Signal Layer 2 w25: v4(87.5,1540) 87.5,120 120,87.5 4287.5,87.5 TP3.1@4650,450 4700,500 L1.6@4700,1211.06
  other v1: 4980,780 5040,780 5100,780 5160,780 5220,780 5280,780 5340,780 5400,780 4980,2230 5040,2230 5100,2230 5160,2230 5220,2230 5280,2230 5340,2230 5400,2230
NetC8_2: C8.2 C9.1 D4.2 D5.1 T2.1 T2.2
NetC29_2: C29.2 R28.2 | length 60
  Top Layer w10: R28.2@230,1637.56 C29.2@290,1637.56
NetC30_1: C30.1 R34.2 U1.4 | length 203.4
  Top Layer w10: R34.2@237.56,1439.33 245.12,1431.77 280,1431.77 318.23,1431.77 376.02,1373.98 U1.4@413.86,1373.98
NetC31_1: C31.1 R34.1 | length 50
  Top Layer w10: R34.1@182.44,1439.33 C31.1@182.44,1489.33
NetC33_1: C33.1 R31.1 U1.23 | length 181
  Top Layer w10: U1.23@646.14,1425.16 695.16,1425.16 710,1440 710,1497.56 C33.1@707.56,1500
  Top Layer w25: C33.1@707.56,1500 R31.1@707.56,1550
NetC35_1: C35.1 U1.5 | length 153.3
  Top Layer w10: C35.1@277.56,1389.33 330.67,1389.33 371.61,1348.39 U1.5@413.86,1348.39
NetC40_1: C40.1 U4.2 | length 94.8
  Top Layer w25: U4.2@1957.28,1615 2005,1615 v1(2010,1610) v1(2050,1610)
NetC41_1: C41.1 U5.2 | length 94.8
  Top Layer w25: U5.2@1947.28,1145 1995,1145 v1(2000,1140) v1(2040,1140)
NetD1_2: D1.2 J1.1 Q1.5 Q1.6 Q1.7 Q1.8 Q1.9 Q4.5 Q4.6 Q4.7 Q4.8 Q4.9 Q5.5 Q5.6 Q5.7 Q5.8 Q5.9 T2.10 T2.11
